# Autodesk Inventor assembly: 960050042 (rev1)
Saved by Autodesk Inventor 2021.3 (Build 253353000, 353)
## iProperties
Created: 2023-03
Part Number: 960050042 (rev1)
Document SubType Name: Assembly
Designer: AdminForWorker
Title: 960050042 (rev1) v2
Author: AdminForWorker
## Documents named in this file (2)
- z:\worker\convert-fusion-r08-cosv3\tmp\job-1\3553\output\files\82b4d9ad-b575-4129-b9ca-4964d6b72adf\960050042 (rev1) v2_4.iam
- z:\worker\convert-fusion-r08-cosv3\tmp\job-1\3553\output\files\82b4d9ad-b575-4129-b9ca-4964d6b72adf\960050042 (rev1).ipt
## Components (1 placed, 1 different names)
1. 960050042 (rev1):1
